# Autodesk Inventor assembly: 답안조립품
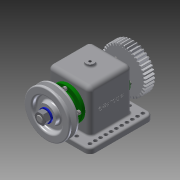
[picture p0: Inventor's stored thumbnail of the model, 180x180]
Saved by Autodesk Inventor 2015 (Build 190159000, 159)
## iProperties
Created: 2018-11
Part Number: 답안조립품
Document SubType Name: Assembly
Designer: now
Author: now
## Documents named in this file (13)
- C:\Users\now\Desktop\481108V1012\답안조립품.iam
- C:\Users\now\Desktop\481108V1012\V벨트풀리.ipt
- C:\Users\now\Desktop\481108V1012\너트 M12x1.25.ipt
- C:\Users\now\Desktop\481108V1012\베어링 6203.ipt
- C:\Users\now\Desktop\481108V1012\본체.ipt
- C:\Users\now\Desktop\481108V1012\볼트 M4.ipt
- C:\Users\now\Desktop\481108V1012\부시.ipt
- C:\Users\now\Desktop\481108V1012\스퍼기어.ipt
- C:\Users\now\Desktop\481108V1012\오일 실 26 38 8.ipt
- C:\Users\now\Desktop\481108V1012\와셔 12x24.ipt
- C:\Users\now\Desktop\481108V1012\축.ipt
- C:\Users\now\Desktop\481108V1012\커버.ipt
- C:\Users\now\Desktop\481108V1012\키 5x5x12.ipt
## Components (1 placed, 1 different names)
1. V벨트풀리:1 — 각도:4
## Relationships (1: Angle 1)
- 각도:4 [Angle]: V벨트풀리:1
